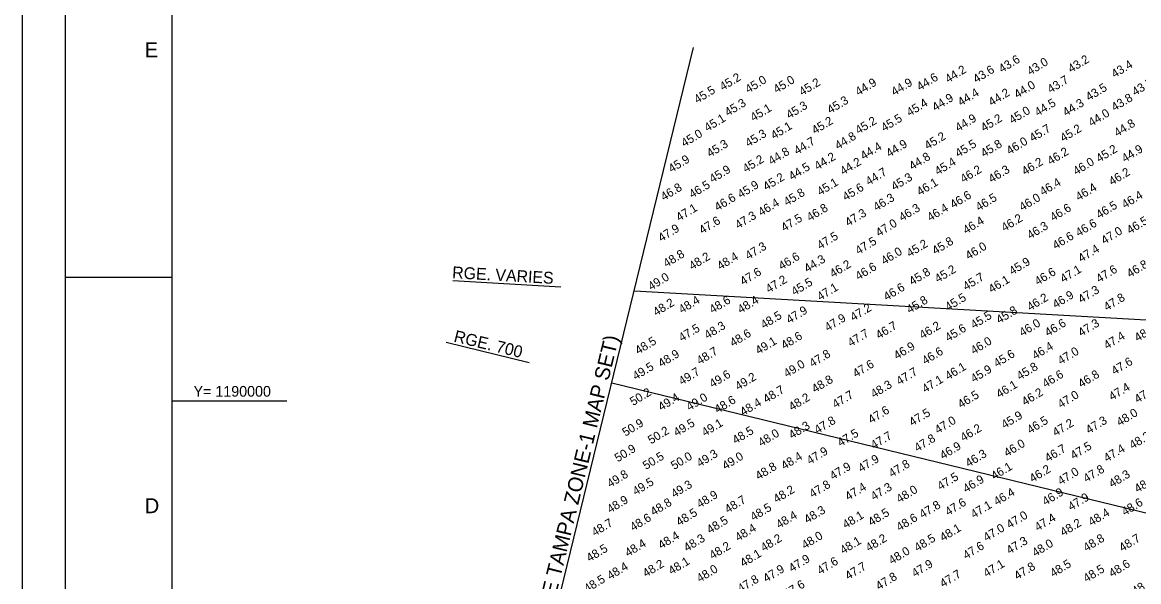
# Model space of a CAD drawing. Extents: x 415488 to 419888, y 1187739 to 1191312.
# Drawn here: x 415488 to 416796, y 1189788 to 1190444 of the extents above; entities that cross this region are included whole.
import ezdxf

# ---------------------------------------------------------------- set-up
doc = ezdxf.new("R2010")
doc.units = 0
for name, color, linetype in [('C-CHAN-POIT', 7, 'Continuous'), ('C-CHAN-WIDE', 7, 'Continuous'), ('G-ANNO-NPLT', 7, 'Continuous'), ('G-ANNO-TTLB', 7, 'Continuous'), ('V-ALGN-TEXT', 7, 'Continuous'), ('V-ANNO-MATC', 7, 'Continuous'), ('V-ANNO-MATC-IDEN', 7, 'Continuous'), ('V-TOPO-COOR-STAT', 7, 'Continuous'), ('V-TOPO-SOUN', 7, 'Continuous')]:
    doc.layers.add(name, color=color, linetype=linetype)

msp = doc.modelspace()

# ---------------------------------------------------------------- linework, layer by layer
at = {"layer": 'C-CHAN-POIT'}
msp.add_line((416179.3, 1190021.3), (417394.7, 1189724.9), dxfattribs=at)
at = {"layer": 'C-CHAN-WIDE'}
msp.add_line((416205.5, 1190128.9), (418985.5, 1189971), dxfattribs=at)
at = {"layer": 'G-ANNO-NPLT'}
msp.add_lwpolyline([(415488.5, 1191311.7), (419888.5, 1191311.7), (419888.5, 1187911.7), (415488.5, 1187911.7)], close=True, dxfattribs=at)
at = {"layer": 'G-ANNO-TTLB'}
msp.add_line((415538.5, 1190144.9), (415663.5, 1190144.9), dxfattribs=at)
for points in [[(415538.5, 1187961.7), (419838.5, 1187961.7), (419838.5, 1191261.7), (415538.5, 1191261.7)], [(419788.5, 1191211.7), (415663.5, 1191211.7), (415663.5, 1188011.7), (419788.5, 1188011.7)]]:
    msp.add_lwpolyline(points, close=True, dxfattribs=at)
at = {"layer": 'V-ALGN-TEXT'}
for p, q in [((415992.9, 1190141), (416119.3, 1190133.8)), ((415985, 1190068.7), (416082.1, 1190045))]:
    msp.add_line(p, q, dxfattribs=at)
at = {"layer": 'V-ANNO-MATC'}
msp.add_line((415942.3, 1189049.8), (416275, 1190414), dxfattribs=at)
at = {"layer": 'V-TOPO-COOR-STAT'}
msp.add_line((415663.5, 1190000), (415798.5, 1190000), dxfattribs=at)

# ---------------------------------------------------------------- texts
at = {"layer": 'G-ANNO-TTLB'}
for s, p in [('E', (415631.9, 1190402.7)), ('D', (415632, 1189868.5))]:
    msp.add_text(s, height=17.5, dxfattribs=at).set_placement(p)
at = {"layer": 'V-ALGN-TEXT'}
for s, rotation, p in [('RGE. VARIES', 356.7498, (415991.8, 1190143.8)), ('RGE. 700', 346.2946, (415993.2, 1190069.6))]:
    msp.add_text(s, height=13.92, rotation=rotation, dxfattribs=at).set_placement(p)
at = {"layer": 'V-ANNO-MATC-IDEN'}
msp.add_text('MATCHLINE SHEET NO. 028 STA. 121+00 EGMONT CUT-2 (SEE TAMPA ZONE-1 MAP SET)', height=17.52, rotation=76.2946, dxfattribs=at).set_placement((415950.7, 1189102.7))
at = {"layer": 'V-TOPO-COOR-STAT'}
msp.add_text('Y= 1190000', height=12.5, dxfattribs=at).set_placement((415689.1, 1190005))
at = {"layer": 'V-TOPO-SOUN'}
for s, p in [('43.6 ', (416636.1, 1190384)), ('43.2 ', (416717.1, 1190384)), ('44.2 ', (416573.1, 1190372)), ('43.6 ', (416606.1, 1190372)), ('43.0 ', (416669.1, 1190381)), ('43.4 ', (416768.1, 1190378)), ('45.2 ', (416309.1, 1190363)), ('45.0 ', (416339.1, 1190360)), ('45.0 ', (416372.1, 1190360)), ('45.2 ', (416402.1, 1190357)), ('44.9 ', (416468.1, 1190357)), ('44.9 ', (416510.1, 1190357)), ('44.6 ', (416540.1, 1190363)), ('43.7 ', (416693.1, 1190360)), ('43.5 ', (416792.1, 1190357)), ('45.5 ', (416279.1, 1190348)), ('44.4 ', (416588.1, 1190345)), ('44.2 ', (416624.1, 1190345)), ('44.0 ', (416654.1, 1190354)), ('43.5 ', (416738.1, 1190351)), ('45.3 ', (416315.1, 1190333)), ('45.3 ', (416435.1, 1190336)), ('45.4 ', (416528.1, 1190333)), ('44.9 ', (416558.1, 1190339)), ('44.5 ', (416678.1, 1190333)), ('44.3 ', (416711.1, 1190333)), ('43.8 ', (416768.1, 1190339)), ('45.1 ', (416345.1, 1190327)), ('45.3 ', (416387.1, 1190330)), ('45.0 ', (416648.1, 1190324)), ('44.0 ', (416741.1, 1190321)), ('45.1 ', (416291.1, 1190315)), ('45.1 ', (416369.1, 1190306)), ('45.2 ', (416417.1, 1190312)), ('45.2 ', (416468.1, 1190312)), ('45.5 ', (416498.1, 1190315)), ('44.9 ', (416585.1, 1190315)), ('45.2 ', (416615.1, 1190315)), ('44.8 ', (416771.1, 1190309)), ('45.0 ', (416264.1, 1190297)), ('45.3 ', (416339.1, 1190297)), ('44.8 ', (416444.1, 1190294)), ('45.2 ', (416549.1, 1190294)), ('45.7 ', (416672.1, 1190303)), ('45.2 ', (416708.1, 1190303)), ('45.3 ', (416294.1, 1190285)), ('44.7 ', (416396.1, 1190288)), ('44.4 ', (416474.1, 1190282)), ('44.9 ', (416504.1, 1190285)), ('45.5 ', (416585.1, 1190285)), ('45.8 ', (416615.1, 1190285)), ('46.0 ', (416645.1, 1190288)), ('45.2 ', (416750.1, 1190279)), ('44.9 ', (416780.1, 1190279)), ('45.9 ', (416249.1, 1190267)), ('45.2 ', (416336.1, 1190267)), ('44.8 ', (416366.1, 1190276)), ('44.2 ', (416420.1, 1190270)), ('44.8 ', (416531.1, 1190270)), ('46.2 ', (416693.1, 1190276)), ('45.9 ', (416297.1, 1190255)), ('44.5 ', (416390.1, 1190258)), ('44.2 ', (416450.1, 1190264)), ('44.7 ', (416480.1, 1190252)), ('45.4 ', (416561.1, 1190264)), ('46.2 ', (416591.1, 1190255)), ('46.3 ', (416624.1, 1190255)), ('46.2 ', (416663.1, 1190264)), ('46.0 ', (416723.1, 1190264)), ('46.2 ', (416765.1, 1190252)), ('45.2 ', (416360.1, 1190246)), ('45.1 ', (416423.1, 1190240)), ('45.3 ', (416510.1, 1190246)), ('46.1 ', (416540.1, 1190240)), ('46.4 ', (416684.1, 1190240)), ('46.8 ', (416240.1, 1190234)), ('46.5 ', (416273.1, 1190237)), ('45.9 ', (416330.1, 1190237)), ('45.8 ', (416384.1, 1190228)), ('45.6 ', (416453.1, 1190234)), ('46.4 ', (416726.1, 1190234)), ('46.6 ', (416303.1, 1190222)), ('46.4 ', (416354.1, 1190216)), ('46.3 ', (416489.1, 1190222)), ('46.6 ', (416579.1, 1190225)), ('46.5 ', (416609.1, 1190222)), ('46.0 ', (416660.1, 1190222)), ('46.5 ', (416750.1, 1190213)), ('46.4 ', (416780.1, 1190225)), ('47.1 ', (416258.1, 1190210)), ('47.3 ', (416327.1, 1190201)), ('46.8 ', (416411.1, 1190210)), ('47.3 ', (416456.1, 1190204)), ('46.3 ', (416519.1, 1190210)), ('46.4 ', (416552.1, 1190210)), ('46.6 ', (416696.1, 1190210)), ('47.6 ', (416285.1, 1190195)), ('47.5 ', (416381.1, 1190198)), ('47.0 ', (416492.1, 1190192)), ('46.4 ', (416594.1, 1190195)), ('46.2 ', (416639.1, 1190198)), ('46.3 ', (416669.1, 1190189)), ('46.6 ', (416726.1, 1190192)), ('46.5 ', (416786.1, 1190195)), ('47.9 ', (416237.1, 1190186)), ('47.5 ', (416423.1, 1190177)), ('46.6 ', (416699.1, 1190177)), ('47.0 ', (416756.1, 1190183)), ('47.3 ', (416339.1, 1190165)), ('47.5 ', (416468.1, 1190171)), ('45.2 ', (416528.1, 1190168)), ('45.8 ', (416558.1, 1190171)), ('46.0 ', (416597.1, 1190165)), ('47.4 ', (416729.1, 1190162)), ('48.8 ', (416243.1, 1190156)), ('48.2 ', (416273.1, 1190153)), ('48.4 ', (416306.1, 1190153)), ('46.6 ', (416378.1, 1190153)), ('44.3 ', (416408.1, 1190150)), ('46.0 ', (416498.1, 1190159)), ('47.6 ', (416333.1, 1190135)), ('46.2 ', (416438.1, 1190144)), ('46.6 ', (416468.1, 1190141)), ('45.8 ', (416531.1, 1190135)), ('45.2 ', (416561.1, 1190138)), ('45.9 ', (416648.1, 1190147)), ('46.6 ', (416678.1, 1190135)), ('47.1 ', (416708.1, 1190138)), ('47.6 ', (416750.1, 1190138)), ('46.8 ', (416786.1, 1190144)), ('49.0 ', (416225.1, 1190129)), ('47.2 ', (416363.1, 1190126)), ('45.5 ', (416393.1, 1190123)), ('45.7 ', (416594.1, 1190129)), ('46.1 ', (416624.1, 1190126)), ('47.1 ', (416423.1, 1190117)), ('46.6 ', (416501.1, 1190117)), ('46.9 ', (416699.1, 1190108)), ('47.3 ', (416729.1, 1190114)), ('48.2 ', (416231.1, 1190099)), ('48.4 ', (416261.1, 1190102)), ('48.6 ', (416297.1, 1190102)), ('48.4 ', (416330.1, 1190102)), ('45.8 ', (416528.1, 1190102)), ('45.5 ', (416573.1, 1190105)), ('46.2 ', (416669.1, 1190105)), ('47.8 ', (416759.1, 1190105)), ('48.5 ', (416357.1, 1190084)), ('47.9 ', (416387.1, 1190090)), ('47.2 ', (416462.1, 1190093)), ('45.5 ', (416603.1, 1190084)), ('45.8 ', (416633.1, 1190090)), ('47.5 ', (416261.1, 1190069)), ('48.3 ', (416291.1, 1190072)), ('47.9 ', (416432.1, 1190081)), ('46.7 ', (416492.1, 1190072)), ('46.2 ', (416543.1, 1190072)), ('45.6 ', (416573.1, 1190069)), ('46.0 ', (416660.1, 1190075)), ('46.6 ', (416690.1, 1190075)), ('47.3 ', (416729.1, 1190075)), ('48.4 ', (416795.1, 1190069)), ('48.6 ', (416321.1, 1190063)), ('48.6 ', (416381.1, 1190060)), ('47.7 ', (416459.1, 1190063)), ('47.4 ', (416759.1, 1190060)), ('48.5 ', (416210.1, 1190054)), ('48.7 ', (416282.1, 1190042)), ('49.1 ', (416351.1, 1190054)), ('46.9 ', (416513.1, 1190048)), ('46.0 ', (416603.1, 1190054)), ('46.4 ', (416675.1, 1190048)), ('48.9 ', (416237.1, 1190039)), ('47.8 ', (416414.1, 1190039)), ('46.6 ', (416546.1, 1190042)), ('45.6 ', (416630.1, 1190039)), ('47.0 ', (416705.1, 1190042)), ('47.6 ', (416768.1, 1190030)), ('49.5 ', (416207.1, 1190024)), ('49.7 ', (416261.1, 1190018)), ('49.0 ', (416384.1, 1190027)), ('47.6 ', (416465.1, 1190027)), ('47.7 ', (416516.1, 1190018)), ('46.1 ', (416573.1, 1190024)), ('45.9 ', (416603.1, 1190021)), ('45.8 ', (416657.1, 1190024)), ('49.6 ', (416297.1, 1190015)), ('49.2 ', (416327.1, 1190012)), ('48.8 ', (416417.1, 1190009)), ('47.1 ', (416546.1, 1190009)), ('46.6 ', (416687.1, 1190015)), ('46.8 ', (416729.1, 1190015)), ('50.2 ', (416204.1, 1189994)), ('48.7 ', (416360.1, 1189997)), ('47.7 ', (416441.1, 1189991)), ('48.3 ', (416486.1, 1190003)), ('46.5 ', (416588.1, 1189991)), ('46.1 ', (416633.1, 1190003)), ('46.2 ', (416663.1, 1189994)), ('47.0 ', (416705.1, 1189991)), ('47.4 ', (416765.1, 1190000)), ('47.9 ', (416795.1, 1189997)), ('49.4 ', (416237.1, 1189988)), ('49.0 ', (416270.1, 1189988)), ('48.6 ', (416303.1, 1189985)), ('48.4 ', (416333.1, 1189982)), ('48.2 ', (416390.1, 1189988)), ('47.6 ', (416483.1, 1189973)), ('47.5 ', (416531.1, 1189970)), ('45.9 ', (416639.1, 1189967)), ('48.0 ', (416774.1, 1189970)), ('50.9 ', (416195.1, 1189958)), ('49.5 ', (416255.1, 1189958)), ('49.1 ', (416288.1, 1189958)), ('48.3 ', (416390.1, 1189955)), ('47.8 ', (416420.1, 1189961)), ('47.0 ', (416561.1, 1189961)), ('46.2 ', (416591.1, 1189952)), ('46.5 ', (416669.1, 1189961)), ('47.2 ', (416699.1, 1189958)), ('47.3 ', (416738.1, 1189961)), ('50.2 ', (416225.1, 1189949)), ('48.5 ', (416324.1, 1189949)), ('48.0 ', (416354.1, 1189946)), ('47.5 ', (416447.1, 1189946)), ('47.7 ', (416486.1, 1189943)), ('47.8 ', (416537.1, 1189940)), ('48.2 ', (416789.1, 1189943)), ('50.9 ', (416186.1, 1189928)), ('47.9 ', (416411.1, 1189925)), ('46.9 ', (416567.1, 1189931)), ('46.0 ', (416642.1, 1189934)), ('46.7 ', (416690.1, 1189928)), ('47.5 ', (416720.1, 1189931)), ('47.4 ', (416759.1, 1189928)), ('50.5 ', (416219.1, 1189919)), ('50.0 ', (416252.1, 1189919)), ('49.3 ', (416282.1, 1189922)), ('49.0 ', (416312.1, 1189919)), ('48.4 ', (416381.1, 1189919)), ('47.9 ', (416471.1, 1189916)), ('46.3 ', (416597.1, 1189922)), ('48.8 ', (416351.1, 1189907)), ('47.9 ', (416438.1, 1189907)), ('47.8 ', (416507.1, 1189910)), ('46.1 ', (416627.1, 1189907)), ('46.2 ', (416672.1, 1189904)), ('47.0 ', (416705.1, 1189901)), ('47.8 ', (416735.1, 1189904)), ('49.8 ', (416177.1, 1189898)), ('49.5 ', (416207.1, 1189889)), ('49.3 ', (416252.1, 1189886)), ('47.8 ', (416414.1, 1189886)), ('47.5 ', (416564.1, 1189895)), ('46.9 ', (416594.1, 1189892)), ('48.3 ', (416765.1, 1189898)), ('48.9 ', (416795.1, 1189892)), ('48.9 ', (416282.1, 1189874)), ('48.2 ', (416372.1, 1189880)), ('47.4 ', (416456.1, 1189883)), ('47.3 ', (416486.1, 1189883)), ('48.0 ', (416516.1, 1189880)), ('46.4 ', (416630.1, 1189877)), ('46.9 ', (416687.1, 1189877)), ('48.9 ', (416177.1, 1189868)), ('48.8 ', (416228.1, 1189865)), ('48.7 ', (416315.1, 1189868)), ('47.8 ', (416543.1, 1189862)), ('47.6 ', (416573.1, 1189865)), ('47.1 ', (416603.1, 1189862)), ('47.9 ', (416717.1, 1189871)), ('48.6 ', (416780.1, 1189865)), ('48.6 ', (416204.1, 1189847)), ('48.5 ', (416258.1, 1189853)), ('48.5 ', (416345.1, 1189859)), ('48.4 ', (416375.1, 1189850)), ('48.3 ', (416408.1, 1189856)), ('48.1 ', (416453.1, 1189850)), ('48.5 ', (416483.1, 1189853)), ('48.6 ', (416516.1, 1189847)), ('47.0 ', (416645.1, 1189850)), ('47.4 ', (416678.1, 1189847)), ('48.4 ', (416741.1, 1189853)), ('48.7 ', (416159.1, 1189841)), ('48.5 ', (416294.1, 1189844)), ('48.4 ', (416327.1, 1189835)), ('48.1 ', (416567.1, 1189835)), ('47.0 ', (416618.1, 1189835)), ('48.2 ', (416708.1, 1189841)), ('48.4 ', (416237.1, 1189826)), ('48.3 ', (416267.1, 1189823)), ('48.2 ', (416357.1, 1189823)), ('48.0 ', (416405.1, 1189826)), ('48.2 ', (416480.1, 1189823)), ('48.5 ', (416537.1, 1189823)), ('48.8 ', (416735.1, 1189823)), ('48.7 ', (416777.1, 1189823)), ('48.5 ', (416153.1, 1189811)), ('48.4 ', (416198.1, 1189817)), ('48.2 ', (416297.1, 1189814)), ('48.1 ', (416450.1, 1189820)), ('48.0 ', (416507.1, 1189808)), ('47.6 ', (416594.1, 1189814)), ('47.3 ', (416645.1, 1189820)), ('48.0 ', (416675.1, 1189817)), ('48.1 ', (416249.1, 1189796)), ('48.1 ', (416333.1, 1189805)), ('47.9 ', (416390.1, 1189799)), ('47.6 ', (416423.1, 1189796)), ('48.4 ', (416177.1, 1189790)), ('48.2 ', (416219.1, 1189793)), ('48.0 ', (416282.1, 1189787)), ('47.9 ', (416360.1, 1189787)), ('47.7 ', (416456.1, 1189790)), ('47.9 ', (416534.1, 1189793)), ('47.7 ', (416567.1, 1189781)), ('47.1 ', (416618.1, 1189793)), ('47.8 ', (416654.1, 1189790)), ('48.5 ', (416696.1, 1189793)), ('48.5 ', (416735.1, 1189787)), ('48.6 ', (416765.1, 1189793)), ('48.5 ', (416150.1, 1189775)), ('47.8 ', (416330.1, 1189775)), ('47.6 ', (416384.1, 1189769)), ('47.8 ', (416492.1, 1189778)), ('48.4 ', (416792.1, 1189772))]:
    msp.add_text(s, height=10, rotation=31.2939, dxfattribs=at).set_placement(p)

doc.saveas('drawing.dxf')
